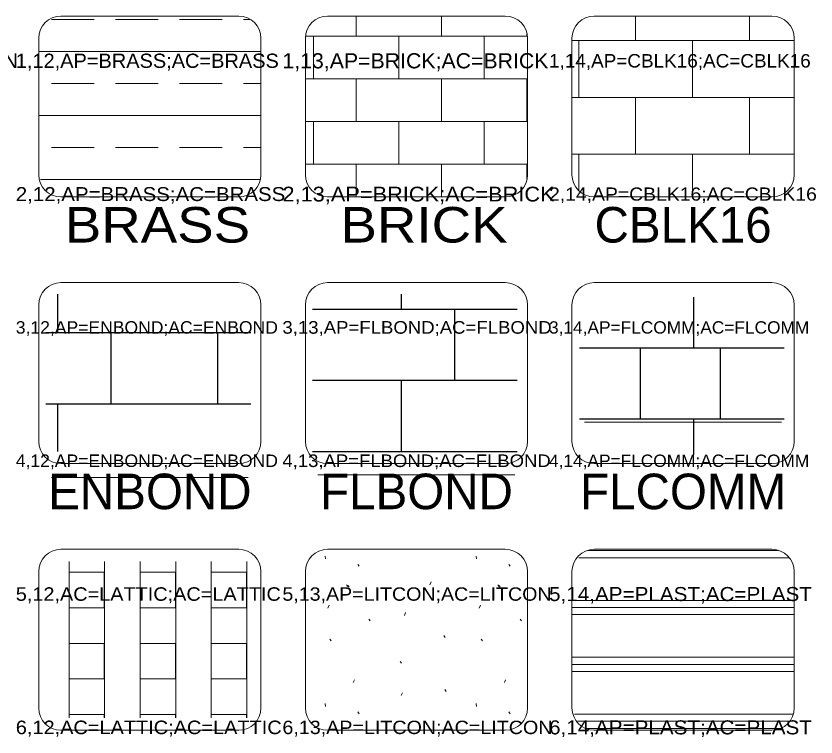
# Model space of a CAD drawing. Extents: x 95935 to 95946.4, y 95971.2 to 95974.7.
# Drawn here: x 95941.635 to 95943.435, y 95973.109 to 95974.732 of the extents above; entities that cross this region are included whole.
import ezdxf
from ezdxf.enums import TextEntityAlignment as Align

# ---------------------------------------------------------------- set-up
doc = ezdxf.new("R2010")
doc.units = 0
doc.header["$LTSCALE"] = 0.013
for name, color, linetype, lineweight in [('1', 7, 'Continuous', 13), ('25', 7, 'Continuous', 13), ('6', 7, 'Continuous', 13), ('63', 7, 'Continuous', 13)]:
    doc.layers.add(name, color=color, linetype=linetype, lineweight=lineweight)
doc.layers.add('20', color=7, linetype='Continuous')

msp = doc.modelspace()

# ---------------------------------------------------------------- linework, layer by layer
at = {"layer": '1'}
for p, q in [((95941.7357, 95974.7318), (95942.1357, 95974.7318)), ((95942.3357, 95974.7318), (95942.7357, 95974.7318)), ((95942.9357, 95974.7318), (95943.3357, 95974.7318)), ((95941.6857, 95974.3747), (95941.6857, 95974.6818)), ((95942.1857, 95974.6818), (95942.1857, 95974.3747)), ((95942.2857, 95974.3747), (95942.2857, 95974.6818)), ((95942.7857, 95974.6818), (95942.7857, 95974.3747)), ((95942.8857, 95974.3747), (95942.8857, 95974.6818)), ((95943.3857, 95974.6818), (95943.3857, 95974.3747)), ((95942.1357, 95974.3247), (95941.7357, 95974.3247)), ((95942.7357, 95974.3247), (95942.3357, 95974.3247)), ((95943.3357, 95974.3247), (95942.9357, 95974.3247)), ((95941.7357, 95974.1318), (95942.1357, 95974.1318)), ((95942.3357, 95974.1318), (95942.7357, 95974.1318)), ((95942.9357, 95974.1318), (95943.3357, 95974.1318)), ((95941.6857, 95973.7747), (95941.6857, 95974.0818)), ((95942.1857, 95974.0818), (95942.1857, 95973.7747)), ((95942.2857, 95973.7747), (95942.2857, 95974.0818)), ((95942.7857, 95974.0818), (95942.7857, 95973.7747)), ((95942.8857, 95973.7747), (95942.8857, 95974.0818)), ((95943.3857, 95974.0818), (95943.3857, 95973.7747)), ((95942.1357, 95973.7247), (95941.7357, 95973.7247)), ((95942.7357, 95973.7247), (95942.3357, 95973.7247)), ((95943.3357, 95973.7247), (95942.9357, 95973.7247)), ((95941.7357, 95973.5318), (95942.1357, 95973.5318)), ((95942.3357, 95973.5318), (95942.7357, 95973.5318)), ((95942.9357, 95973.5318), (95943.3357, 95973.5318)), ((95941.6857, 95973.1747), (95941.6857, 95973.4818)), ((95942.1857, 95973.4818), (95942.1857, 95973.1747)), ((95942.2857, 95973.1747), (95942.2857, 95973.4818)), ((95942.7857, 95973.4818), (95942.7857, 95973.1747)), ((95942.8857, 95973.1747), (95942.8857, 95973.4818)), ((95943.3857, 95973.4818), (95943.3857, 95973.1747)), ((95942.1357, 95973.1247), (95941.7357, 95973.1247)), ((95942.7357, 95973.1247), (95942.3357, 95973.1247)), ((95943.3357, 95973.1247), (95942.9357, 95973.1247))]:
    msp.add_line(p, q, dxfattribs=at)
for centre, start, end in [((95941.7357, 95974.6818), 90, 180), ((95942.1357, 95974.6818), 0, 90), ((95942.3357, 95974.6818), 90, 180), ((95942.7357, 95974.6818), 0, 90), ((95942.9357, 95974.6818), 90, 180), ((95943.3357, 95974.6818), 0, 90), ((95941.7357, 95974.3747), 180, 270), ((95942.1357, 95974.3747), 270, 0), ((95942.3357, 95974.3747), 180, 270), ((95942.7357, 95974.3747), 270, 0), ((95942.9357, 95974.3747), 180, 270), ((95943.3357, 95974.3747), 270, 0), ((95941.7357, 95974.0818), 90, 180), ((95942.1357, 95974.0818), 0, 90), ((95942.3357, 95974.0818), 90, 180), ((95942.7357, 95974.0818), 0, 90), ((95942.9357, 95974.0818), 90, 180), ((95943.3357, 95974.0818), 0, 90), ((95941.7357, 95973.7747), 180, 270), ((95942.1357, 95973.7747), 270, 0), ((95942.3357, 95973.7747), 180, 270), ((95942.7357, 95973.7747), 270, 0), ((95942.9357, 95973.7747), 180, 270), ((95943.3357, 95973.7747), 270, 0), ((95941.7357, 95973.4818), 90, 180), ((95942.1357, 95973.4818), 0, 90), ((95942.3357, 95973.4818), 90, 180), ((95942.7357, 95973.4818), 0, 90), ((95942.9357, 95973.4818), 90, 180), ((95943.3357, 95973.4818), 0, 90), ((95941.7357, 95973.1747), 180, 270), ((95942.1357, 95973.1747), 270, 0), ((95942.3357, 95973.1747), 180, 270), ((95942.7357, 95973.1747), 270, 0), ((95942.9357, 95973.1747), 180, 270), ((95943.3357, 95973.1747), 270, 0)]:
    msp.add_arc(centre, 0.05, start, end, dxfattribs=at)
at = {"layer": '25'}
for p, q in [((95943.3569, 95973.8178), (95942.9141, 95973.8178)), ((95942.1569, 95973.6934), (95941.7141, 95973.6934)), ((95942.7569, 95973.6996), (95942.3141, 95973.6996))]:
    msp.add_line(p, q, dxfattribs=at)
at = {"layer": '6'}
for p, q in [((95941.7145, 95974.7242), (95941.8105, 95974.7242)), ((95941.8585, 95974.7242), (95941.9545, 95974.7242)), ((95942.0025, 95974.7242), (95942.0985, 95974.7242)), ((95942.1465, 95974.7242), (95942.1605, 95974.7242)), ((95942.3998, 95974.7318), (95942.3998, 95974.6863)), ((95942.5918, 95974.7318), (95942.5918, 95974.6863)), ((95943.0289, 95974.6767), (95943.0289, 95974.7318)), ((95943.2849, 95974.6767), (95943.2849, 95974.7318)), ((95942.7838, 95974.6914), (95942.7838, 95974.6863)), ((95942.8857, 95974.6767), (95943.3857, 95974.6767)), ((95942.9009, 95974.5487), (95942.9009, 95974.6767)), ((95943.1569, 95974.5487), (95943.1569, 95974.6767)), ((95941.6857, 95974.6522), (95942.1857, 95974.6522)), ((95941.7145, 95974.5802), (95941.8105, 95974.5802)), ((95941.8585, 95974.5802), (95941.9545, 95974.5802)), ((95942.0025, 95974.5802), (95942.0985, 95974.5802)), ((95942.1465, 95974.5802), (95942.1857, 95974.5802)), ((95942.3998, 95974.5903), (95942.3998, 95974.4943)), ((95942.5918, 95974.5903), (95942.5918, 95974.4943)), ((95942.6878, 95974.5903), (95942.7857, 95974.5903)), ((95942.7838, 95974.5903), (95942.7838, 95974.4943)), ((95942.8857, 95974.5487), (95943.3857, 95974.5487)), ((95943.0289, 95974.4207), (95943.0289, 95974.5487)), ((95943.2849, 95974.4207), (95943.2849, 95974.5487)), ((95941.6857, 95974.5082), (95942.1857, 95974.5082)), ((95941.7145, 95974.4362), (95941.8105, 95974.4362)), ((95941.8585, 95974.4362), (95941.9545, 95974.4362)), ((95942.0025, 95974.4362), (95942.0985, 95974.4362)), ((95942.1465, 95974.4362), (95942.1857, 95974.4362)), ((95942.8857, 95974.4207), (95943.3857, 95974.4207)), ((95942.9009, 95974.3389), (95942.9009, 95974.4207)), ((95943.1569, 95974.3247), (95943.1569, 95974.4207)), ((95942.3998, 95974.3983), (95942.3998, 95974.3247)), ((95942.5918, 95974.3983), (95942.5918, 95974.3247)), ((95942.6878, 95974.3983), (95942.7857, 95974.3983)), ((95942.7838, 95974.3983), (95942.7838, 95974.3652)), ((95941.69, 95974.3642), (95942.1836, 95974.3642)), ((95942.33, 95973.5167), (95942.3307, 95973.5103)), ((95942.6703, 95973.5167), (95942.671, 95973.5103)), ((95942.9206, 95973.5288), (95943.3508, 95973.5288)), ((95941.7539, 95973.504), (95941.7539, 95973.1527)), ((95941.8339, 95973.504), (95941.8339, 95973.1527)), ((95941.9139, 95973.504), (95941.9139, 95973.1527)), ((95941.9939, 95973.504), (95941.9939, 95973.1527)), ((95942.0739, 95973.504), (95942.0739, 95973.1527)), ((95942.1539, 95973.504), (95942.1539, 95973.1527)), ((95942.4037, 95973.4978), (95942.4066, 95973.4935)), ((95942.744, 95973.4978), (95942.7469, 95973.4935)), ((95942.9014, 95973.5128), (95943.374, 95973.5128)), ((95941.8339, 95973.48), (95941.7539, 95973.48)), ((95941.9939, 95973.48), (95941.9139, 95973.48)), ((95942.1539, 95973.48), (95942.0739, 95973.48)), ((95942.3785, 95973.4521), (95942.3813, 95973.4478)), ((95942.3813, 95973.4505), (95942.3841, 95973.4462)), ((95942.566, 95973.4521), (95942.5689, 95973.4585)), ((95942.7188, 95973.4521), (95942.7216, 95973.4478)), ((95942.7216, 95973.4505), (95942.7244, 95973.4462)), ((95942.3365, 95973.3994), (95942.3394, 95973.4058)), ((95942.6768, 95973.3994), (95942.6797, 95973.4058)), ((95942.8857, 95973.4168), (95943.3857, 95973.4168)), ((95941.8339, 95973.4), (95941.7539, 95973.4)), ((95941.9939, 95973.4), (95941.9139, 95973.4)), ((95942.1539, 95973.4), (95942.0739, 95973.4)), ((95942.5085, 95973.3831), (95942.5113, 95973.3895)), ((95942.8857, 95973.4008), (95943.3857, 95973.4008)), ((95942.4289, 95973.3748), (95942.4318, 95973.3705)), ((95942.7692, 95973.3748), (95942.7721, 95973.3705)), ((95942.8857, 95973.3848), (95943.3857, 95973.3848)), ((95942.5973, 95973.3376), (95942.6001, 95973.3334)), ((95941.8339, 95973.32), (95941.7539, 95973.32)), ((95941.9939, 95973.32), (95941.9139, 95973.32)), ((95942.1539, 95973.32), (95942.0739, 95973.32)), ((95942.3409, 95973.3299), (95942.3438, 95973.3257)), ((95942.6812, 95973.3299), (95942.6841, 95973.3257)), ((95942.499, 95973.2795), (95942.5019, 95973.2752)), ((95942.8857, 95973.2888), (95943.3857, 95973.2888)), ((95942.8857, 95973.2728), (95943.3857, 95973.2728)), ((95942.8857, 95973.2568), (95943.3857, 95973.2568)), ((95941.8339, 95973.24), (95941.7539, 95973.24)), ((95941.9939, 95973.24), (95941.9139, 95973.24)), ((95942.1539, 95973.24), (95942.0739, 95973.24)), ((95942.3934, 95973.2318), (95942.3962, 95973.2382)), ((95942.7337, 95973.2318), (95942.7365, 95973.2382)), ((95942.5014, 95973.2026), (95942.5042, 95973.209)), ((95942.5999, 95973.2164), (95942.6028, 95973.2121)), ((95942.33, 95973.1848), (95942.3307, 95973.1784)), ((95942.6703, 95973.1848), (95942.671, 95973.1784)), ((95941.8339, 95973.16), (95941.7539, 95973.16)), ((95941.9939, 95973.16), (95941.9139, 95973.16)), ((95942.1539, 95973.16), (95942.0739, 95973.16)), ((95942.4037, 95973.166), (95942.4066, 95973.1617)), ((95942.744, 95973.166), (95942.7469, 95973.1617)), ((95942.8914, 95973.1608), (95943.3829, 95973.1608)), ((95942.898, 95973.1448), (95943.3747, 95973.1448)), ((95942.568, 95973.1247), (95942.5689, 95973.1266)), ((95942.9161, 95973.1288), (95943.3553, 95973.1288))]:
    msp.add_line(p, q, dxfattribs=at)
at = {"layer": '6', "lineweight": 25}
for p, q in [((95941.7286, 95974.0193), (95941.7286, 95974.1056)), ((95942.5024, 95974.0722), (95942.5024, 95974.1056)), ((95943.1596, 95973.9854), (95943.1596, 95974.099)), ((95942.302, 95974.0722), (95942.7627, 95974.0722)), ((95942.6224, 95973.9122), (95942.6224, 95974.0722)), ((95941.702, 95974.0193), (95942.1627, 95974.0193)), ((95941.8486, 95973.8593), (95941.8486, 95974.0193)), ((95942.0886, 95973.8593), (95942.0886, 95974.0193)), ((95942.9029, 95973.9854), (95943.3636, 95973.9854)), ((95943.0396, 95973.8254), (95943.0396, 95973.9854)), ((95943.2196, 95973.8254), (95943.2196, 95973.9854)), ((95942.302, 95973.9122), (95942.7627, 95973.9122)), ((95942.5024, 95973.7522), (95942.5024, 95973.9122)), ((95941.702, 95973.8593), (95942.1627, 95973.8593)), ((95941.7286, 95973.7517), (95941.7286, 95973.8593)), ((95942.9029, 95973.8254), (95943.3636, 95973.8254)), ((95943.1596, 95973.7451), (95943.1596, 95973.8254)), ((95942.302, 95973.7522), (95942.7627, 95973.7522)), ((95942.6224, 95973.7517), (95942.6224, 95973.7522)), ((95941.8339, 95973.4), (95941.8339, 95973.48)), ((95941.9939, 95973.4), (95941.9939, 95973.48)), ((95942.1539, 95973.4), (95942.1539, 95973.48)), ((95941.8339, 95973.24), (95941.8339, 95973.32)), ((95941.9939, 95973.24), (95941.9939, 95973.32)), ((95942.1539, 95973.24), (95942.1539, 95973.32)), ((95941.8339, 95973.1527), (95941.8339, 95973.16)), ((95941.9939, 95973.1527), (95941.9939, 95973.16)), ((95942.1539, 95973.1527), (95942.1539, 95973.16))]:
    msp.add_line(p, q, dxfattribs=at)
at = {"layer": '6'}
for points in [[(95942.2857, 95974.5903), (95942.3038, 95974.5903), (95942.3038, 95974.6863), (95942.2866, 95974.6863)], [(95942.7848, 95974.6863), (95942.6878, 95974.6863), (95942.6878, 95974.5903)], [(95942.2857, 95974.3983), (95942.3038, 95974.3983), (95942.3038, 95974.4943), (95942.2857, 95974.4943)], [(95942.7857, 95974.4943), (95942.6878, 95974.4943), (95942.6878, 95974.3983)]]:
    msp.add_lwpolyline(points, dxfattribs=at)
for points in [[(95942.3038, 95974.5903), (95942.4958, 95974.5903), (95942.4958, 95974.6863), (95942.3038, 95974.6863)], [(95942.4958, 95974.5903), (95942.6878, 95974.5903), (95942.6878, 95974.6863), (95942.4958, 95974.6863)], [(95942.3038, 95974.3983), (95942.4958, 95974.3983), (95942.4958, 95974.4943), (95942.3038, 95974.4943)], [(95942.4958, 95974.3983), (95942.6878, 95974.3983), (95942.6878, 95974.4943), (95942.4958, 95974.4943)]]:
    msp.add_lwpolyline(points, close=True, dxfattribs=at)

# ---------------------------------------------------------------- texts
at = {"layer": '20', "width": 1.15}
for s, p in [(' BRASS', (95941.9358, 95974.222)), (' BRICK', (95942.5357, 95974.222))]:
    msp.add_text(s, height=0.08, dxfattribs=at).set_placement(p, align=Align.CENTER)
at = {"layer": '20'}
for s, p in [('CBLK16', (95943.1358, 95974.222)), ('ENBOND', (95941.9358, 95973.622)), ('FLBOND', (95942.5358, 95973.622)), ('FLCOMM', (95943.1358, 95973.622))]:
    msp.add_text(s, height=0.08, dxfattribs=at).set_placement(p, align=Align.CENTER)
at = {"layer": '63'}
for s, height, width, p in [('1,11,AP=BATEN;AC=BATEN', 0.033, 1.05, (95941.0341, 95974.6146)), ('1,12,AP=BRASS;AC=BRASS', 0.032, 1.05, (95941.6341, 95974.6151)), ('1,13,AP=BRICK;AC=BRICK', 0.0341, 1.05, (95942.2341, 95974.614)), ('1,14,AP=CBLK16;AC=CBLK16', 0.0303, 1.05, (95942.8341, 95974.6159)), ('2,12,AP=BRASS;AC=BRASS', 0.0313, 1.1, (95941.6341, 95974.3154)), ('2,13,AP=BRICK;AC=BRICK', 0.0333, 1.1, (95942.2341, 95974.3144)), ('2,14,AP=CBLK16;AC=CBLK16', 0.0296, 1.1, (95942.8341, 95974.3163)), ('3,12,AP=ENBOND;AC=ENBOND', 0.0281, 1.05, (95941.6341, 95974.017)), ('3,13,AP=FLBOND;AC=FLBOND', 0.0284, 1.1, (95942.2341, 95974.0169)), ('3,14,AP=FLCOMM;AC=FLCOMM', 0.0277, 1.05, (95942.8341, 95974.0172)), ('4,12,AP=ENBOND;AC=ENBOND', 0.0281, 1.05, (95941.6341, 95973.717)), ('4,13,AP=FLBOND;AC=FLBOND', 0.0283, 1.1, (95942.2341, 95973.7169)), ('4,14,AP=FLCOMM;AC=FLCOMM', 0.0277, 1.05, (95942.8341, 95973.7172)), ('5,12,AC=LATTIC;AC=LATTIC', 0.0304, 1.1, (95941.6341, 95973.4159)), ('5,13,AP=LITCON;AC=LITCON', 0.03, 1.1, (95942.2341, 95973.4161)), ('5,14,AP=PLAST;AC=PLAST', 0.0316, 1.1, (95942.8341, 95973.4153)), ('6,12,AC=LATTIC;AC=LATTIC', 0.0305, 1.1, (95941.6341, 95973.1158)), ('6,13,AP=LITCON;AC=LITCON', 0.0301, 1.1, (95942.2341, 95973.116)), ('6,14,AP=PLAST;AC=PLAST', 0.0316, 1.1, (95942.8341, 95973.1153))]:
    msp.add_text(s, height=height, dxfattribs=dict(at, width=width)).set_placement(p)

doc.saveas('drawing.dxf')
